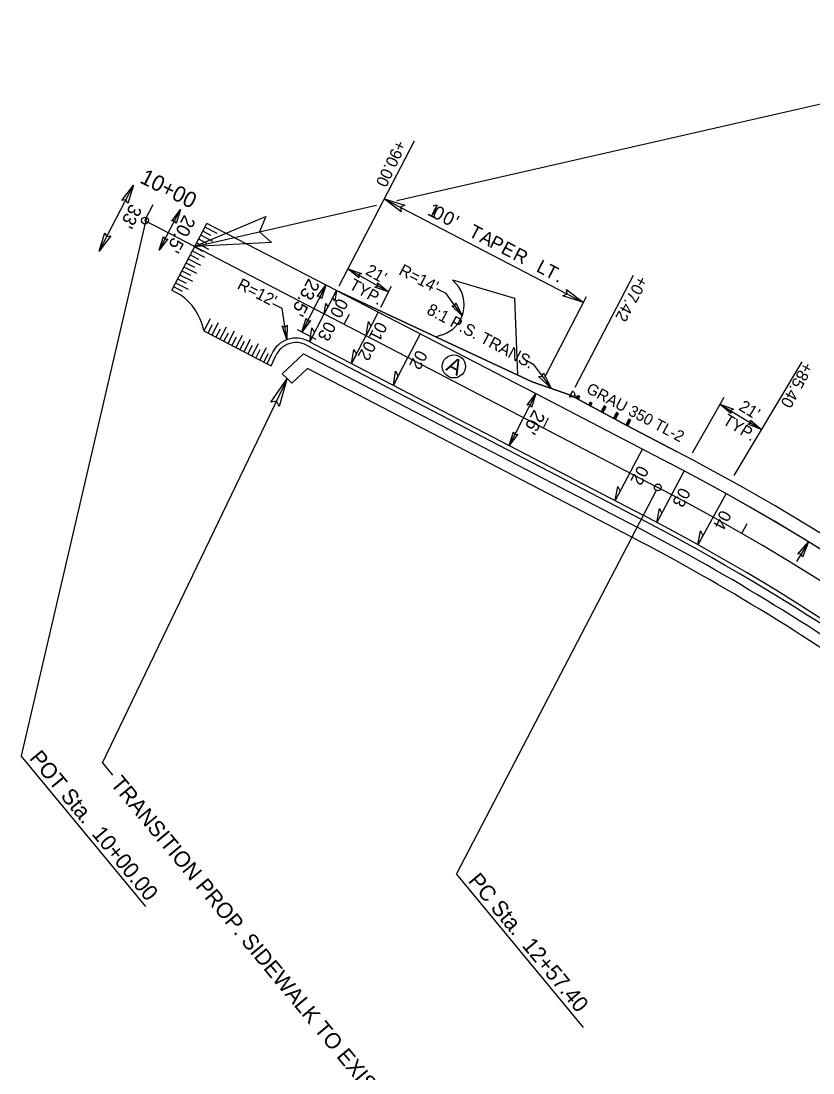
# Model space of a CAD drawing. Extents: x 2057680 to 2059216, y 687940 to 689338.
# Drawn here: x 2058269.7 to 2058622.3, y 688713 to 689181.4 of the extents above; entities that cross this region are included whole.
import ezdxf

# ---------------------------------------------------------------- set-up
doc = ezdxf.new("R2010")
doc.units = 0
for name, color, linetype in [('Cogo Default Point CELL', 7, 'Continuous'), ('COGO Default Point Number', 7, 'Continuous'), ('Exist DTM Breakline Cogo Elevation', 7, 'Continuous'), ('Exist DTM Breakline Cogo Point CELL', 7, 'Continuous'), ('Exist DTM Regular Point Cogo Number', 7, 'Continuous'), ('Exist DTM Regular Point Underwater Cogo Number', 7, 'Continuous'), ('Exist DTM Ridgeline Cogo Number', 7, 'Continuous'), ('Exist DTM Ridgeline Cogo Point CELL', 7, 'Continuous'), ('Exist Other Culture Located Object CELL', 7, 'Continuous'), ('Exist Other Culture Located Object Leader', 7, 'Continuous'), ('Exist Roads EOP Cogo Elevation', 7, 'Continuous'), ('Exist Roads EOP Cogo Number', 7, 'Continuous'), ('Exist Roads EOP Cogo Point CELL', 7, 'Continuous'), ('Exist Roads Soil', 7, 'Continuous'), ('Exist Structure Major Bridge WW Cogo Point CELL', 7, 'Continuous'), ('Exist Structure Major Deck Tunnel Box Culvert Cogo Elevation', 7, 'Continuous'), ('Exist Structure Major Deck Tunnel Box Culvert Cogo Number', 7, 'Continuous'), ('Exist Structure Major Deck Tunnel Box Culvert Cogo Point CELL', 7, 'Continuous'), ('Exist Structure Minor Pipes HDPE 36 Inch', 7, 'Continuous'), ('Prop Conc 2ft 6in Curb and Gutter', 7, 'Continuous')]:
    doc.layers.add(name, color=color, linetype=linetype)

msp = doc.modelspace()

# ---------------------------------------------------------------- linework, layer by layer
at = {"layer": 'Cogo Default Point CELL'}
msp.add_line((2058324.9, 689092.58), (2058553.22, 688973.76), dxfattribs=at)
msp.add_arc((2058091.57, 688086.7), 1000, 13.85856, 62.50587, dxfattribs=at)
at = {"layer": 'COGO Default Point Number'}
msp.add_circle((2058462.42, 689027.65), 5.14, dxfattribs=at)
at = {"layer": 'Exist DTM Breakline Cogo Elevation'}
for p, q in [((2058437.11, 689101.57), (2058787.36, 689181.43)), ((2058347.08, 689081.04), (2058427.94, 689099.48)), ((2058354.29, 689085.98), (2058350.63, 689087.83)), ((2058356.97, 689086.86), (2058351.53, 689089.61)), ((2058353.36, 689079.72), (2058347.92, 689082.47)), ((2058352.48, 689082.41), (2058348.82, 689084.26)), ((2058355.17, 689083.29), (2058349.73, 689086.04)), ((2058351.56, 689076.15), (2058346.12, 689078.9)), ((2058350.68, 689078.84), (2058347.02, 689080.69)), ((2058347.07, 689071.7), (2058343.22, 689073.64)), ((2058349.75, 689072.58), (2058344.31, 689075.33)), ((2058348.87, 689075.27), (2058345.21, 689077.12)), ((2058345.26, 689068.13), (2058341.38, 689070.09)), ((2058347.95, 689069.01), (2058342.3, 689071.87)), ((2058415.18, 689071.1), (2058433.36, 689060.77)), ((2058344.34, 689061.87), (2058338.61, 689064.77)), ((2058343.45, 689064.56), (2058339.53, 689066.54)), ((2058346.14, 689065.44), (2058340.45, 689068.32)), ((2058341.65, 689060.99), (2058337.68, 689063)), ((2058429.91, 689054.07), (2058434.67, 689063.32)), ((2058459.05, 689060.1), (2058454.85, 689062.14)), ((2058466.12, 689050.14), (2058459.05, 689060.1)), ((2058385.97, 689053.48), (2058381.77, 689055.52)), ((2058388.03, 689039.57), (2058385.97, 689053.48)), ((2058353.97, 689048.84), (2058351.15, 689043.43)), ((2058354.82, 689046.14), (2058352.92, 689042.51)), ((2058357.51, 689046.99), (2058354.69, 689041.58)), ((2058361.06, 689045.14), (2058358.24, 689039.74)), ((2058358.36, 689044.29), (2058356.47, 689040.66)), ((2058361.91, 689042.44), (2058360.01, 689038.81)), ((2058364.61, 689043.29), (2058361.79, 689037.89)), ((2058365.46, 689040.59), (2058363.56, 689036.96)), ((2058368.15, 689041.44), (2058365.33, 689036.04)), ((2058369, 689038.74), (2058367.11, 689035.11)), ((2058371.7, 689039.59), (2058368.88, 689034.19)), ((2058372.55, 689036.89), (2058370.65, 689033.26)), ((2058375.25, 689037.74), (2058372.43, 689032.34)), ((2058378.79, 689035.89), (2058375.97, 689030.49)), ((2058376.1, 689035.05), (2058374.2, 689031.41)), ((2058379.64, 689033.2), (2058377.75, 689029.56)), ((2058305.94, 688851.16), (2058388.32, 689022.29)), ((2058498.95, 689015.53), (2058487.04, 688992.42)), ((2058580.89, 689010.87), (2058599.39, 688999.53))]:
    msp.add_line(p, q, dxfattribs=at)
at = {"layer": 'Exist DTM Breakline Cogo Point CELL'}
for p in [(2058517.42, 689013.19), (2058561.54, 688989.73)]:
    msp.add_line(p, (2058539.38, 689001.26), dxfattribs=at)
msp.add_arc((2058091.57, 688086.7), 1018.01, 47.4643, 62.50587, dxfattribs=at)
at = {"layer": 'Exist DTM Regular Point Cogo Number'}
for points in [[(2058314.66, 689101.54), (2058319.85, 689108.35), (2058317.26, 689100.13), (2058316.43, 689101.78)], [(2058438.98, 689096.54), (2058431.41, 689102.3), (2058440.54, 689099.42), (2058438.71, 689098.5)], [(2058309.68, 689085.74), (2058304.48, 689078.93), (2058307.08, 689087.14), (2058307.91, 689085.49)], [(2058512.55, 689061.89), (2058520.12, 689056.13), (2058510.99, 689059.01), (2058512.82, 689059.93)], [(2058502.31, 689024.72), (2058505.74, 689017.93), (2058500.18, 689023.2), (2058501.82, 689023.22)]]:
    msp.add_lwpolyline(points, close=True, dxfattribs=at)
at = {"layer": 'Exist DTM Regular Point Underwater Cogo Number'}
msp.add_line((2058561.53, 688989.72), (2058539.38, 689001.25), dxfattribs=at)
msp.add_arc((2058091.57, 688086.7), 1018, 47.4643, 62.50587, dxfattribs=at)
at = {"layer": 'Exist DTM Ridgeline Cogo Number'}
for p, q in [((2058410.13, 689061.4), (2058404.74, 689051.03)), ((2058398.27, 689038.62), (2058404.74, 689051.03)), ((2058428.79, 689051.76), (2058423.36, 689041.34)), ((2058416.9, 689028.92), (2058423.36, 689041.34)), ((2058447.45, 689042.13), (2058441.99, 689031.65)), ((2058435.53, 689019.23), (2058441.99, 689031.65)), ((2058546.48, 688990.93), (2058534.32, 688967.95)), ((2058565.04, 688981.11), (2058552.88, 688958.13)), ((2058583.72, 688970.97), (2058571.07, 688948.25))]:
    msp.add_line(p, q, dxfattribs=at)
for points in [[(2058410.13, 689061.4), (2058409.38, 689056.71), (2058408.52, 689058.32)], [(2058404.74, 689051.03), (2058405.46, 689055.72), (2058406.32, 689054.12)], [(2058423.36, 689041.34), (2058424.35, 689047.59), (2058425.49, 689045.45)], [(2058398.27, 689038.62), (2058399.26, 689044.86), (2058400.4, 689042.72)], [(2058416.9, 689028.92), (2058417.89, 689035.17), (2058419.03, 689033.03)], [(2058435.53, 689019.23), (2058436.51, 689025.47), (2058437.66, 689023.33)], [(2058534.32, 688967.95), (2058535.37, 688974.19), (2058536.49, 688972.04)], [(2058552.88, 688958.13), (2058553.93, 688964.36), (2058555.05, 688962.21)], [(2058571.07, 688948.25), (2058572.2, 688954.47), (2058573.3, 688952.3)]]:
    msp.add_lwpolyline(points, close=True, dxfattribs=at)
at = {"layer": 'Exist DTM Ridgeline Cogo Point CELL'}
for p, q in [((2058513.97, 689014.09), (2058515.38, 689016.67)), ((2058514.24, 689013.94), (2058513.97, 689014.09)), ((2058515.68, 689014.13), (2058514.24, 689013.94)), ((2058515.65, 689016.52), (2058515.38, 689016.67)), ((2058515.65, 689016.52), (2058516.27, 689015.21)), ((2058516.27, 689015.21), (2058515.68, 689014.13)), ((2058516.98, 689013.43), (2058515.68, 689014.13)), ((2058516.03, 689014.77), (2058517.32, 689014.06)), ((2058516.97, 689013.42), (2058517.69, 689014.75)), ((2058518.57, 689014.28), (2058516.97, 689013.42)), ((2058517.85, 689012.94), (2058516.97, 689013.42)), ((2058517.41, 689013.18), (2058539.38, 689001.25)), ((2058518.57, 689014.28), (2058517.69, 689014.75)), ((2058517.85, 689012.94), (2058517.69, 689014.75)), ((2058517.85, 689012.94), (2058518.57, 689014.28)), ((2058522.46, 689010.44), (2058523.19, 689011.77)), ((2058524.07, 689011.3), (2058522.46, 689010.44)), ((2058523.34, 689009.96), (2058522.46, 689010.44)), ((2058524.07, 689011.3), (2058523.19, 689011.77)), ((2058523.34, 689009.96), (2058523.19, 689011.77)), ((2058523.34, 689009.96), (2058524.07, 689011.3)), ((2058527.96, 689007.46), (2058529.4, 689010.12)), ((2058529.56, 689008.31), (2058527.96, 689007.46)), ((2058528.68, 689008.79), (2058530.28, 689009.65)), ((2058529.56, 689008.31), (2058528.68, 689008.79)), ((2058528.83, 689006.98), (2058528.68, 689008.79)), ((2058528.83, 689006.98), (2058530.28, 689009.65)), ((2058530.28, 689009.65), (2058529.4, 689010.12)), ((2058529.4, 689010.12), (2058529.56, 689008.31)), ((2058528.83, 689006.98), (2058527.96, 689007.46)), ((2058533.45, 689004.47), (2058534.9, 689007.14)), ((2058535.05, 689005.33), (2058533.45, 689004.47)), ((2058534.33, 689004), (2058533.45, 689004.47)), ((2058534.17, 689005.81), (2058535.78, 689006.66)), ((2058535.05, 689005.33), (2058534.17, 689005.81)), ((2058534.33, 689004), (2058534.17, 689005.81)), ((2058534.33, 689004), (2058535.78, 689006.66)), ((2058535.78, 689006.66), (2058534.9, 689007.14)), ((2058534.9, 689007.14), (2058535.05, 689005.33)), ((2058538.94, 689001.49), (2058540.39, 689004.16)), ((2058539.66, 689002.83), (2058541.27, 689003.68)), ((2058540.54, 689002.35), (2058539.66, 689002.83)), ((2058539.82, 689001.01), (2058539.66, 689002.83)), ((2058539.82, 689001.01), (2058541.27, 689003.68)), ((2058541.27, 689003.68), (2058540.39, 689004.16)), ((2058540.39, 689004.16), (2058540.54, 689002.35)), ((2058540.54, 689002.35), (2058538.94, 689001.49)), ((2058539.82, 689001.01), (2058538.94, 689001.49))]:
    msp.add_line(p, q, dxfattribs=at)
at = {"layer": 'Exist Other Culture Located Object CELL'}
for p, q in [((2058444.74, 689127.9), (2058411.17, 689063.4)), ((2058304.48, 689078.93), (2058319.85, 689108.35)), ((2058431.41, 689102.3), (2058520.12, 689056.13)), ((2058331.18, 689079.33), (2058340.66, 689097.47)), ((2058405.39, 689063.86), (2058394.69, 689042.92)), ((2058542.28, 689068.07), (2058516.32, 689018.19)), ((2058521.39, 689058.56), (2058502.75, 689022.75)), ((2058401.1, 689039.63), (2058392.8, 689043.89)), ((2058494.85, 689030.2), (2058497.81, 689028.65)), ((2058497.81, 689028.65), (2058505.74, 689017.93)), ((2058617.42, 689029.7), (2058587.02, 688978.98)), ((2058582.69, 689013.73), (2058568.59, 688989.05)), ((2058620.37, 688949.55), (2058614.94, 688940.7)), ((2058305.94, 688851.16), (2058310.49, 688845.56))]:
    msp.add_line(p, q, dxfattribs=at)
at = {"layer": 'Exist Roads EOP Cogo Elevation'}
for p, q in [((2058386, 689024.38), (2058395.5, 689033.29)), ((2058395.5, 689033.29), (2058543.99, 688956.01)), ((2058397.2, 689026.77), (2058390.29, 689020.23)), ((2058541.68, 688951.58), (2058397.2, 689026.77))]:
    msp.add_line(p, q, dxfattribs=at)
msp.add_lwpolyline([(2058390.29, 689020.23), (2058388.27, 689022.19), (2058386, 689024.38)], dxfattribs=at)
for radius in [980, 975]:
    msp.add_arc((2058091.57, 688086.7), radius, 54.28994, 62.50587, dxfattribs=at)
at = {"layer": 'Exist Roads EOP Cogo Number'}
for p, q in [((2058413.61, 689046.42), (2058415.91, 689050.85)), ((2058502.31, 689000.25), (2058504.62, 689004.69)), ((2058590.59, 688953.29), (2058593.08, 688957.62))]:
    msp.add_line(p, q, dxfattribs=at)
at = {"layer": 'Exist Roads EOP Cogo Point CELL'}
for p, q in [((2058325.59, 689093.91), (2058269.71, 688854.29)), ((2058552.53, 688972.42), (2058463.67, 688801.68)), ((2058325.3, 688787.06), (2058269.71, 688854.29)), ((2058520.22, 688733.3), (2058463.67, 688801.68))]:
    msp.add_line(p, q, dxfattribs=at)
for centre in [(2058324.9, 689092.58), (2058553.22, 688973.76)]:
    msp.add_circle(centre, 1.5, dxfattribs=at)
at = {"layer": 'Exist Structure Major Bridge WW Cogo Point CELL'}
for p, q in [((2058410.13, 689061.4), (2058497.36, 689020.7)), ((2058497.36, 689020.7), (2058514.37, 689014.83))]:
    msp.add_line(p, q, dxfattribs=at)
msp.add_lwpolyline([(2058514.37, 689014.83), (2058539.38, 689001.25), (2058561.53, 688989.72)], dxfattribs=at)
msp.add_arc((2058091.57, 688086.7), 1018, 47.4643, 62.50587, dxfattribs=at)
at = {"layer": 'Exist Structure Major Deck Tunnel Box Culvert Cogo Elevation'}
for p, q in [((2058497.36, 689020.7), (2058410.13, 689061.4)), ((2058410.13, 689061.4), (2058498.93, 689015.54)), ((2058514.37, 689014.83), (2058497.36, 689020.7)), ((2058498.93, 689015.54), (2058558.76, 688984.4))]:
    msp.add_line(p, q, dxfattribs=at)
msp.add_lwpolyline([(2058561.53, 688989.72), (2058539.38, 689001.25), (2058514.37, 689014.83)], dxfattribs=at)
for radius, start in [(1018, 47.4643), (1012, 46.48931)]:
    msp.add_arc((2058091.57, 688086.7), radius, start, 62.50587, dxfattribs=at)
at = {"layer": 'Exist Structure Major Deck Tunnel Box Culvert Cogo Number'}
for p, q in [((2058336.92, 689061.53), (2058352.44, 689091.34)), ((2058463.3, 689064.61), (2058461.84, 689066.18)), ((2058461.84, 689066.18), (2058489.42, 689058.03)), ((2058336.92, 689061.53), (2058340.72, 689059.49)), ((2058410.13, 689061.4), (2058498.93, 689015.54)), ((2058489.42, 689058.03), (2058490.76, 689023.78)), ((2058351.02, 689044.23), (2058351.15, 689043.43)), ((2058351.15, 689043.43), (2058379.26, 689028.8)), ((2058454.28, 689040.8), (2058457.3, 689041.77)), ((2058397.76, 689038.88), (2058546.76, 688961.34)), ((2058379.26, 689028.8), (2058381.34, 689033.29)), ((2058498.93, 689015.54), (2058558.76, 688984.4))]:
    msp.add_line(p, q, dxfattribs=at)
msp.add_lwpolyline([(2058410.13, 689061.4), (2058352.44, 689091.34)], dxfattribs=at)
for centre, radius, start, end in [((2058453.03, 689055.1), 14, 287.7557, 42.7983), ((2058326.02, 689038.47), 25.65, 12.9773, 55.0366), ((2058392.22, 689028.24), 12, 62.5059, 155.0955), ((2058091.57, 688086.7), 1012, 13.85856, 62.50587), ((2058091.57, 688086.7), 986, 13.85856, 62.50587)]:
    msp.add_arc(centre, radius, start, end, dxfattribs=at)
at = {"layer": 'Exist Structure Major Deck Tunnel Box Culvert Cogo Point CELL'}
msp.add_line((2058324.9, 689092.58), (2058328.59, 689099.68), dxfattribs=at)
at = {"layer": 'Exist Structure Minor Pipes HDPE 36 Inch'}
for points in [[(2058336.79, 689092.37), (2058340.66, 689097.47), (2058338.74, 689091.33), (2058338.11, 689092.56)], [(2058381.18, 689082.88), (2058346.98, 689081.06), (2058378.75, 689094.44), (2058375.87, 689087.63)], [(2058335.04, 689084.42), (2058331.18, 689079.33), (2058333.1, 689085.47), (2058333.72, 689084.23)], [(2058420.13, 689067.06), (2058415.18, 689071.1), (2058421.25, 689068.96), (2058419.99, 689068.38)], [(2058401.53, 689058.77), (2058405.39, 689063.86), (2058403.47, 689057.72), (2058402.85, 689058.95)], [(2058428.41, 689064.81), (2058433.36, 689060.77), (2058427.29, 689062.9), (2058428.54, 689063.48)], [(2058463.36, 689055.9), (2058466.12, 689050.14), (2058461.54, 689054.65), (2058462.92, 689054.65)], [(2058388.18, 689045.96), (2058388.03, 689039.57), (2058385.99, 689045.67), (2058387.22, 689045.04)], [(2058398.55, 689048.01), (2058394.69, 689042.92), (2058396.61, 689049.06), (2058397.23, 689047.83)], [(2058380.87, 689011.74), (2058388.12, 689021.91), (2058384.71, 689009.81), (2058383.43, 689012.18)], [(2058495.1, 689010.43), (2058498.95, 689015.53), (2058497.04, 689009.39), (2058496.42, 689010.61)], [(2058585.71, 689006.67), (2058580.89, 689010.87), (2058586.88, 689008.54), (2058585.61, 689008)], [(2058594.57, 689003.73), (2058599.39, 688999.53), (2058593.4, 689001.87), (2058594.67, 689002.41)], [(2058490.89, 688997.52), (2058487.04, 688992.42), (2058488.95, 688998.56), (2058489.57, 688997.33)], [(2058615.55, 688944.06), (2058620.37, 688949.55), (2058617.67, 688942.71), (2058617.06, 688944.16)]]:
    msp.add_lwpolyline(points, close=True, dxfattribs=at)
at = {"layer": 'Prop Conc 2ft 6in Curb and Gutter'}
for p, q in [((2058396.84, 689037.11), (2058545.84, 688959.56)), ((2058381.07, 689027.96), (2058383.15, 689032.45)), ((2058379.26, 689028.8), (2058381.07, 689027.96))]:
    msp.add_line(p, q, dxfattribs=at)
for centre, radius, start, end in [((2058392.22, 689028.24), 10, 62.5059, 155.0955), ((2058091.57, 688086.7), 984, 49.25135, 62.50587)]:
    msp.add_arc(centre, radius, start, end, dxfattribs=at)

# ---------------------------------------------------------------- texts
at = {"layer": 'COGO Default Point Number'}
msp.add_text('A', height=7, rotation=332.5059, dxfattribs=at).set_placement((2058458.47, 689026.15))
at = {"layer": 'Exist DTM Breakline Cogo Elevation'}
for s, height, rotation, p in [('+90.00', 5.25, 244.7961, (2058436.75, 689128.84)), ("33'", 6, 242.2581, (2058318.55, 689100.41)), ('1', 6, 332.5059, (2058450.25, 689095.36)), ('0', 6, 332.5059, (2058452.34, 689094.27)), ('0', 6, 332.5059, (2058456.79, 689091.96)), ("20.5'", 6, 242.2581, (2058342.4, 689095.43)), ("'", 6, 332.5059, (2058461.23, 689089.64)), ('T', 6, 332.5059, (2058468.56, 689085.83)), ('A', 6, 332.5059, (2058473.42, 689083.3)), ('P', 6, 332.5059, (2058477.86, 689080.99)), ('E', 6, 332.5059, (2058482.98, 689078.33)), ('R', 6, 332.5059, (2058488.26, 689075.58)), ("R=14'", 5.25, 332.7742, (2058437.51, 689068.78)), ('L', 6, 332.5059, (2058498.69, 689070.15)), ('T', 6, 332.5059, (2058502.46, 689068.18)), ("21'", 5.25, 330.3994, (2058422.67, 689068.89)), ("R=12'", 5.25, 332.7742, (2058365.56, 689062.47)), ("23.5'", 6, 242.2581, (2058397.74, 689067.17)), ('TYP.', 5.25, 330.3994, (2058415.37, 689062.47)), ('.', 6, 332.5059, (2058507.32, 689065.66)), ('+07.42', 5.25, 241.2264, (2058544.58, 689068.45)), ('8:1 P.S. TRANS.', 5.25, 331.8262, (2058449.94, 689051.31)), ('+85.40', 5.25, 241.2264, (2058618.15, 689030.08)), ("21'", 5.25, 328.497, (2058588.88, 689008.5)), ("26'", 6, 241.2523, (2058498.18, 689008.72)), ('TYP.', 5.25, 328.497, (2058581.73, 689002.28)), ('TRANSITION PROP. SIDEWALK TO EXISTING', 7, 309.6672, (2058309.24, 688841.63))]:
    msp.add_text(s, height=height, rotation=rotation, dxfattribs=at).set_placement(p)
at = {"layer": 'Exist DTM Ridgeline Cogo Point CELL'}
msp.add_text('GRAU 350 TL-2', height=5, rotation=332.0179, dxfattribs=at).set_placement((2058520.97, 689016.19))
at = {"layer": 'Exist Other Culture Located Object Leader'}
for s, p in [('00', (2058410.78, 689058.41)), ('03', (2058405.36, 689048.1)), ('01', (2058428.17, 689048)), ('02', (2058423.22, 689039.4)), ('02', (2058446.1, 689035.37)), ('02', (2058544.62, 688983.9)), ('03', (2058563.23, 688974.1)), ('04', (2058581.41, 688964.08))]:
    msp.add_text(s, height=5.5, rotation=242.6247, dxfattribs=at).set_placement(p)
at = {"layer": 'Exist Roads EOP Cogo Point CELL'}
for s, rotation, p in [('POT Sta.  10+00.00', 309.4764, (2058273.12, 688853.06)), ('PC Sta.  12+57.40', 309.786, (2058468.46, 688798.39))]:
    msp.add_text(s, height=7, rotation=rotation, dxfattribs=at).set_placement(p)
at = {"layer": 'Exist Roads Soil'}
msp.add_text('10+00', height=7, rotation=332.904, dxfattribs=at).set_placement((2058322.16, 689109.68))

doc.saveas('drawing.dxf')
